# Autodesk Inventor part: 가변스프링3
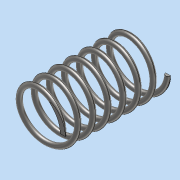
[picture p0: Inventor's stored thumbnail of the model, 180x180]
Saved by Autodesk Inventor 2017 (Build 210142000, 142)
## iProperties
Part Number: 가변스프링3
Material: 스테인레스 스틸
Document SubType Name: Modeling
Designer: MRC
Density: 8 g/cm^3
Appearance: 반연마
Mass: 10.9393 g
Surface Area: 27.6351 cm^2
Volume: 1.36741 cm^3
Author: MRC
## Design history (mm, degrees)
sketch "스케치1"
  geometry: L1 (0, 0)-(10, 0); L2 (10, 0)-(10, 41.411); L3 (10, 41.411)-(0, 41.411); L4 (0, 41.411)-(0, 0); C1 r 1 at (10, 0)
  constraints: 8 end point, 2 parallel, 1 centre point, 1 coincident, 1 horizontal, 1 perpendicular
  dimensions: "d0" = 41.4112 distance of L3.end L1.start (derived); "d1" = 20 diameter of L2 L4; "d2" = 2 diameter of C1
feature "코일1" sketch "스케치1" pitch "d3" = 10; turns "d5" = 7; dims "d4" = 41.4112 (= d0), "d6" = 0, angle "d7" = 90 deg, angle "d8" = 90 deg, "d9" = 0, "d10" = 0
sketch "스케치2"
  geometry: L1 (-25, 41.411)-(25, 41.411); L2 (25, 41.411)-(25, 0); L3 (25, 0)-(-25, 0); L4 (-25, 0)-(-25, 41.411); L5 (0, 41.411)-(0, 0) reference; 2 further points
  constraints: 8 end point, 2 midpoint, 2 parallel, 1 coincident, 1 horizontal, 1 perpendicular
  dimensions: "d11" = 50 distance of L1.start L1.end
extrude "돌출1" sketch "스케치2" stored distance "d12" = 0; taper "d13" = 0 deg
node "솔리드1"
